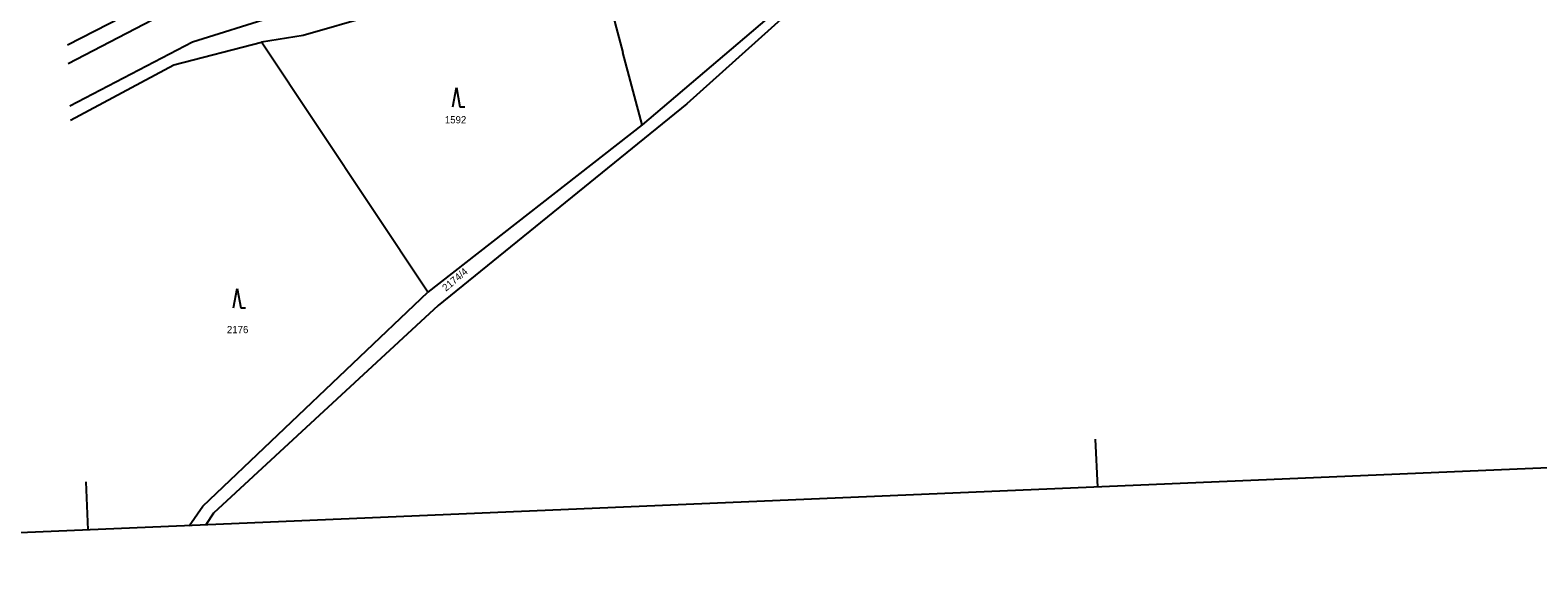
# Model space of a CAD drawing. Extents: x -806456 to -805395, y -1150847 to -1150506.
# Drawn here: x -806245.9 to -805932.5, y -1150847.3 to -1150734.5 of the extents above; entities that cross this region are included whole.
import ezdxf

# ---------------------------------------------------------------- set-up
doc = ezdxf.new("R2010")
doc.units = 0
for name, color, linetype in [('Default', 7, 'Continuous'), ('formát', 7, 'Continuous'), ('kn_celek - Cisla pozemkovych parcel', 7, 'Continuous'), ('kn_celek - Hranice parcel', 7, 'Continuous'), ('kn_celek - Vnitrni kresby', 7, 'Continuous'), ('kn_celek - Znacky kultur', 7, 'Continuous')]:
    doc.layers.add(name, color=color, linetype=linetype)

# ---------------------------------------------------------------- blocks, each defined once
blk = doc.blocks.new('308')
at = {"layer": 'Default'}
for p, q in [((-7.5, 0.2), (0, 40.2)), ((0, 40.2), (7.5, 0.2)), ((7.5, 0.2), (17.5, 0.2))]:
    blk.add_line(p, q, dxfattribs=at)

msp = doc.modelspace()

# ---------------------------------------------------------------- linework, layer by layer
at = {"layer": 'formát'}
for p, q in [((-806024.47, -1150819.52), (-806024.04, -1150829.52)), ((-805814.23, -1150820.61), (-806443.66, -1150847.33)), ((-806234.28, -1150828.43), (-806233.85, -1150838.42))]:
    msp.add_line(p, q, dxfattribs=at)
at = {"layer": 'kn_celek - Hranice parcel'}
for p, q in [((-806069.54, -1150712.39), (-806118.66, -1150754.19)), ((-806066.25, -1150711.08), (-806109.37, -1150749.85)), ((-806238.13, -1150737.6), (-806212.4, -1150724.39)), ((-806126.75, -1150723.7), (-806122.65, -1150739.16)), ((-806174.63, -1150731.47), (-806189.1, -1150735.63)), ((-806215.97, -1150741.78), (-806197.75, -1150737.03)), ((-806189.1, -1150735.63), (-806197.75, -1150737.03)), ((-806163.18, -1150789.01), (-806197.75, -1150737.03)), ((-806237.47, -1150753.23), (-806215.97, -1150741.78)), ((-806118.66, -1150754.19), (-806122.65, -1150739.16)), ((-806109.37, -1150749.85), (-806161.04, -1150791.77)), ((-806118.66, -1150754.19), (-806163.18, -1150789.01)), ((-806209.99, -1150833.49), (-806163.18, -1150789.01)), ((-806161.04, -1150791.77), (-806207.76, -1150834.95)), ((-806212.81, -1150837.53), (-806209.99, -1150833.49)), ((-806207.76, -1150834.95), (-806209.32, -1150837.38))]:
    msp.add_line(p, q, dxfattribs=at)
at = {"layer": 'kn_celek - Vnitrni kresby'}
for p, q in [((-806213.61, -1150728.85), (-806237.97, -1150741.54)), ((-806212.1, -1150736.94), (-806195.28, -1150731.73)), ((-806237.6, -1150750.27), (-806212.1, -1150736.94))]:
    msp.add_line(p, q, dxfattribs=at)

# ---------------------------------------------------------------- block references
at = {"layer": 'kn_celek - Znacky kultur', "xscale": 0.1, "yscale": 0.10000000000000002}
for p in [(-806157.27, -1150750.48), (-806202.84, -1150792.27)]:
    msp.add_blockref('308', p, dxfattribs=at)

# ---------------------------------------------------------------- texts
at = {"layer": 'kn_celek - Cisla pozemkovych parcel'}
for s, p in [('1592', (-806159.67, -1150753.91)), ('2176', (-806204.97, -1150797.52))]:
    msp.add_text(s, height=1.5, dxfattribs=at).set_placement(p)
msp.add_text('2174/4', height=1.5, rotation=40.0671, dxfattribs=at).set_placement((-806159.44, -1150788.91))

doc.saveas('drawing.dxf')
